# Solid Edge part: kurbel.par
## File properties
Author: Wir
Template: Normal.par
Last saved by: Wir
Revision: 2
Application: Solid Edge
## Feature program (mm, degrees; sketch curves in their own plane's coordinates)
swept protrusion "unnamed SweptProtrusion 1"
sketch for "unnamed Protrusion 1" plane through (0, 0, 0) normal (0, -1, 0) x-axis (1, 0, 0)
extrude "unnamed Protrusion 1" add finite 5 symmetric
sketch for "unnamed Protrusion 2" plane through (-22.5592, 0, 0) normal (-1, 0, 0) x-axis (0, 1, 0)
  circle centre (0, 0) radius 2.5
extrude "unnamed Protrusion 2" add finite 2.5 along +normal
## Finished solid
Body 1: solid body, 18 faces, 32 edges, 16 vertices.
  Faces by surface: plane 14, cylinder 4
  Edges by curve: line 20, circle 10, ellipse 2
Bounding box of the edges (mm): 42.500 x 5.000 x 15.000, from (-25.0592, -2.5, -2.5) to (17.4408, 2.5, 12.5).
Cylindrical faces by radius (mm): R2.5 x4
Planar faces by outward normal: +x 5, +y 1, +z 1, -x 5, -y 1, -z 1
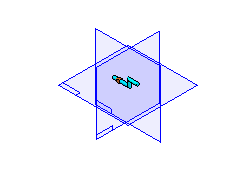
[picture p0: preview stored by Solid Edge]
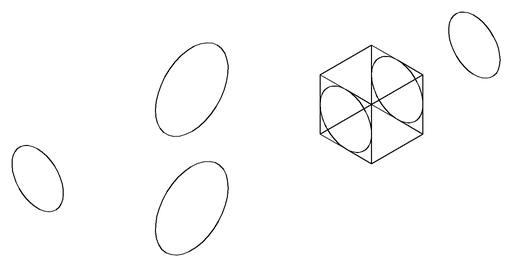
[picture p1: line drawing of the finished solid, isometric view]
